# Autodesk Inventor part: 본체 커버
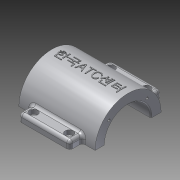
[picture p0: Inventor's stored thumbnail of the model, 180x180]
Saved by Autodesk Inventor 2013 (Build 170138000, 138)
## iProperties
Company: 한국ATC센터
Created: 2014-02
Part Number: 본체 커버
Document SubType Name: Modeling
Designer: KYOUNG IL JANG
Density: 2.71 g/cm^3
Mass: 197.605 g
Surface Area: 197.356 cm^2
Volume: 72.9171 cm^3
Material: 알루미늄-6061
Vendor: CBT Solutions
Author: KYOUNG IL JANG
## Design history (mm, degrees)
sketch "스케치1"
  geometry: L1 (-45, 40)-(45, 40); L2 (45, 40)-(45, -40); L3 (45, -40)-(-45, -40); L4 (-45, -40)-(-45, 40); 3 further points
  constraints: 8 end point, 2 midpoint, 2 parallel, 1 horizontal, 1 horizontal alignment, 1 perpendicular, 1 vertical alignment
  dimensions: "d0" = 90 distance of L2.end L3.end; "d1" = 80 distance of L1.end L2.end
extrude "돌출1" new body sketch "스케치1" distance "d2" = 10; taper "d3" = 0 deg
sketch "스케치2"
  geometry: L1 (40, 0)-(-40, 0) reference; C1 r 32.5 at (0, 80); 2 further points
  constraints: 1 centre point, 1 midpoint, 1 vertical alignment
  dimensions: "d4" = 65 diameter of C1; "d5" = 80 distance from line of C1.centre L1
extrude "돌출2" join sketch "스케치2" stored distance "d6" = 75; taper "d7" = 0 deg
sketch "스케치3"
  geometry: L1 (-7.5, -20)-(7.5, -20); L2 (7.5, 20)-(-7.5, 20); A1 r 20 centre (7.5, 0) between (7.5, -20) and (7.5, 20); A2 r 20 centre (-7.5, 0) between (-7.5, 20) and (-7.5, -20); 2 further points
  constraints: 4 end point, 4 point on circle, 4 tangent, 2 centre point, 1 horizontal, 1 horizontal alignment, 1 midpoint, 1 parallel, 1 vertical alignment
  dimensions: "d8" = 20 radius of A2; "d9" = 55 dimension on A1 A2
extrude "돌출3" join sketch "스케치3" stored distance "d10" = 75; taper "d11" = 0 deg
fillet "모깎기1" dims "d12" = 10
sketch "스케치4"
  geometry: L1 (-45, 0)-(-45, 10) reference; L2 (37.5, 47.5)-(-37.5, 47.5) reference; L3 (-45, 10)-(-27.513, 47.5); 1 further point
  constraints: 2 end point, 1 point on line
  dimensions: "d13" = 25 deg angle of L3 L1
sketch "스케치5"
  geometry: L1 (-40, 0)-(-40, 10) reference; L2 (-40, 10)-(-22.912, 56.95); 2 further points
  constraints: 2 end point, 2 other
  dimensions: "d14" = 20 deg angle of L2 L1
feature "리브1" dims "d15" = 1, "d16" = 6, "d17" = 0
feature "리브2" dims "d18" = 1, "d19" = 6, "d20" = 0
fillet "모깎기2" dims "d21" = 3
fillet "모깎기3" dims "d22" = 3
fillet "모깎기4" dims "d23" = 3
fillet "모깎기5" dims "d24" = 3
fillet "모깎기6" dims "d25" = 3
fillet "모깎기7" dims "d26" = 3
fillet "모깎기8" dims "d27" = 3
sketch "스케치6"
  geometry: A1 r 10 centre (35, -30) between (35, -40) and (45, -30) reference; 1 further point
hole "구멍1" sketch "스케치6" at (35, -30) diameter "d28" = 10; stored, may be unused: countersink angle "d32" = 90 deg, drill point angle "d34" = 118 deg; dims "d29" = 6, "d30" = 4, "d31" = 2, "d33" = 8
hole "구멍2" diameter "d37" = 45; stored, may be unused: countersink angle "d41" = 90 deg, drill point angle "d43" = 118 deg; dims "d35" = 10, "d36" = 10, "d38" = 6, "d39" = 4, "d40" = 2, "d42" = 8
sketch "스케치7"
  geometry: C1 r 22.5 at (0, 0) reference; 2 further points
  dimensions: "d44" = 135 deg dimension on C1.centre point (-18.738, 18.738) point (80, 0); "d45" = 26.5 distance of point (-18.738, 18.738) C1.centre
hole "구멍3" sketch "스케치7" at (-18.738, 18.738) diameter "d46" = 2.459; stored, may be unused: countersink angle "d50" = 90 deg, drill point angle "d52" = 118 deg; dims "d47" = 8, "d48" = 4, "d49" = 2, "d51" = 10
node "작업 평면1"
chamfer "모따기1" distance "d69" = 1; stored, may be unused: second distance "d70" = 2, angle "d71" = 45 deg
sketch "스케치9"
  geometry: L1 (-31.623, 87.5)-(-45, 87.5); L2 (-45, 87.5)-(-45, 72.5); L3 (-45, 72.5)-(-31.623, 72.5); A1 r 32.5 centre (0, 80) between (-31.623, 87.5) and (-31.623, 72.5) reference; 1 further point
  constraints: 6 end point, 2 parallel, 2 point on circle, 1 horizontal, 1 perpendicular
  dimensions: "d73" = 15 distance of L1.end L2.end; "d74" = 45 distance from line of A1.centre L2
extrude "돌출5" join sketch "스케치9" stored distance "d75" = 50; taper "d76" = 0 deg
fillet "모깎기10" dims "d77" = 3
fillet "모깎기11" dims "d78" = 3
sketch "스케치10"
  geometry: L1 (100.378, 66.389)-(0, 66.389); L2 (0, 66.389)-(0, -76.978); L3 (0, -76.978)-(100.378, -76.978); L4 (100.378, -76.978)-(100.378, 66.389); C1 r 32.5 at (0, 0) reference; 1 further point
  constraints: 8 end point, 2 parallel, 1 horizontal, 1 perpendicular, 1 point on line
extrude "돌출6" cut sketch "스케치10" stored distance "d79" = 10; taper "d80" = 0 deg
sketch "스케치11"
  geometry: C1 r 1.621 at (4.5, 4) reference; C2 r 1.621 at (39.5, 4) reference; 1 further point
hole "구멍5" sketch "스케치11" at (39.5, 4), (4.5, 4) diameter "d81" = 4.5; stored, may be unused: countersink angle "d85" = 90 deg, drill point angle "d87" = 118 deg; dims "d82" = 6, "d83" = 8, "d84" = 4.4, "d86" = 8
node "작업 평면2"
sketch "스케치12"
  geometry: 2 further points
  constraints: 1 coincident, 1 other
feature "엠보싱1" sketch "스케치12" dims "d8" = 20, "d9" = 55, "d88" = 0.5, "d89" = 0
node "솔리드1"
mirror "대칭1"
mirror "대칭2"
mirror "대칭3"
mirror "대칭4"
pattern_circular "원형 패턴1" dims angle "d54" = 360 deg
mirror "대칭5"
mirror "대칭6"
mirror "대칭7"
node "참조1"
node "참조2"
other parameters: "d56" = -117
